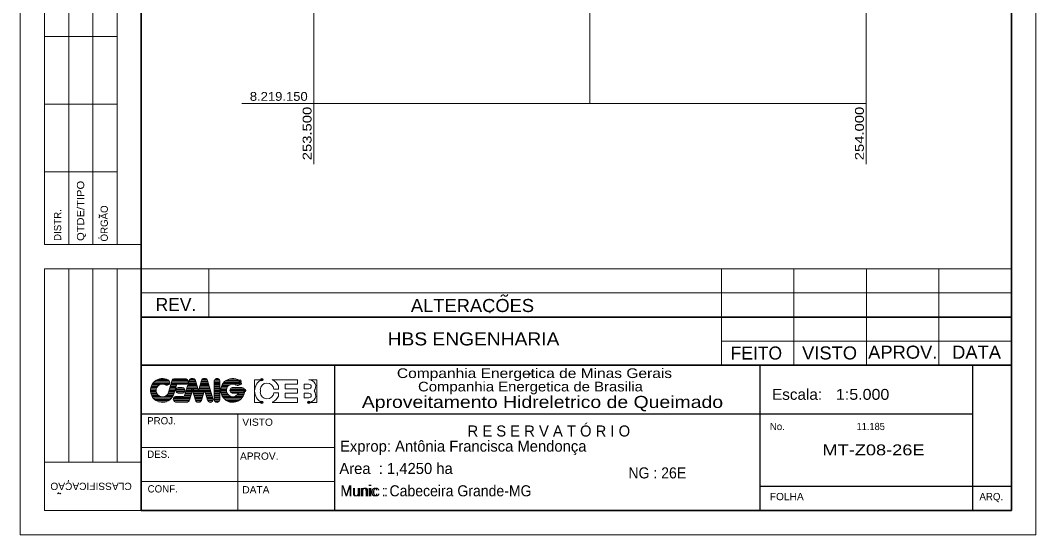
# Model space of a CAD drawing. Extents: x 253235 to 254153, y 8218760 to 8220059.
# Drawn here: x 253235 to 254153, y 8218760 to 8219225 of the extents above; entities that cross this region are included whole.
import ezdxf
from ezdxf.enums import TextEntityAlignment as Align

# ---------------------------------------------------------------- set-up
doc = ezdxf.new("R2010")
doc.units = 0
doc.header["$LTSCALE"] = 4.7
doc.header["$PDMODE"] = 32
doc.header["$PDSIZE"] = 2.35
doc.layers.add('6', color=7, linetype='Continuous', lineweight=13)

msp = doc.modelspace()

# ---------------------------------------------------------------- linework, layer by layer
at = {"layer": '6'}
for p, q in [((253500, 8219095), (253500, 8219900)), ((253750, 8219150), (253750, 8219900)), ((254000, 8219095), (254000, 8219900)), ((253256.41, 8219766.08), (253256.41, 8219022.38)), ((253278.31, 8219766.08), (253278.31, 8219022.38)), ((253300.11, 8219022.38), (253300.11, 8219766.08)), ((253322.01, 8219766.08), (253322.01, 8219022.38)), ((253256.41, 8219210.48), (253322.01, 8219210.48)), ((253256.41, 8219149.28), (253322.01, 8219149.28)), ((253435, 8219150), (254000, 8219150)), ((253256.41, 8219088.08), (253322.01, 8219088.08)), ((253306.31, 8219028.08), (253305.11, 8219028.48)), ((253343.91, 8219022.38), (253256.41, 8219022.38)), ((253278.31, 8218825.48), (253278.31, 8219000.48)), ((253300.11, 8218825.48), (253300.11, 8219000.48)), ((253322.01, 8218825.48), (253322.01, 8219000.48)), ((253343.91, 8219000.48), (254131.41, 8219000.48)), ((253405.11, 8218957.08), (253405.11, 8219000.48)), ((253868.91, 8218913.08), (253868.91, 8219000.48)), ((253934.51, 8219000.48), (253934.51, 8218913.08)), ((254000.11, 8218913.08), (254000.11, 8219000.48)), ((254065.71, 8219000.48), (254065.71, 8218913.08)), ((253343.91, 8218978.68), (254131.41, 8218978.68)), ((253659.91, 8218961.77), (253659.51, 8218960.37)), ((253868.91, 8218934.88), (254131.41, 8218934.88)), ((253353.91, 8218896.08), (253362.71, 8218896.08)), ((253354.71, 8218897.08), (253369.61, 8218897.08)), ((253355.71, 8218898.18), (253369.61, 8218898.18)), ((253356.91, 8218899.28), (253369.11, 8218899.28)), ((253358.91, 8218900.28), (253367.31, 8218900.28)), ((253363.51, 8218896.08), (253369.21, 8218896.08)), ((253371.71, 8218898.88), (253368.61, 8218888.68)), ((253370.91, 8218896.08), (253384.91, 8218896.08)), ((253371.11, 8218897.08), (253386.11, 8218897.08)), ((253371.51, 8218898.18), (253386.41, 8218898.18)), ((253371.71, 8218899.28), (253386.31, 8218899.28)), ((253372.51, 8218900.28), (253385.61, 8218900.28)), ((253383.91, 8218900.88), (253374.11, 8218900.88)), ((253376.91, 8218895.88), (253383.91, 8218895.88)), ((253383.21, 8218885.68), (253387.41, 8218899.28)), ((253386.71, 8218896.68), (253393.71, 8218896.68)), ((253386.91, 8218897.88), (253393.31, 8218897.88)), ((253387.31, 8218898.88), (253393.11, 8218898.88)), ((253387.71, 8218899.88), (253392.71, 8218899.88)), ((253388.91, 8218900.98), (253391.31, 8218900.98)), ((253397.71, 8218896.68), (253404.71, 8218896.68)), ((253398.01, 8218897.88), (253404.51, 8218897.88)), ((253398.31, 8218898.88), (253404.11, 8218898.88)), ((253398.71, 8218899.88), (253403.71, 8218899.88)), ((253400.01, 8218900.98), (253402.51, 8218900.98)), ((253403.91, 8218899.48), (253408.71, 8218883.08)), ((253409.91, 8218898.88), (253415.11, 8218898.88)), ((253409.91, 8218882.08), (253409.91, 8218898.48)), ((253409.91, 8218897.68), (253415.11, 8218897.68)), ((253409.91, 8218896.68), (253415.11, 8218896.68)), ((253410.31, 8218899.88), (253414.71, 8218899.88)), ((253411.51, 8218900.88), (253413.61, 8218900.88)), ((253415.11, 8218898.68), (253415.11, 8218882.08)), ((253417.91, 8218896.68), (253433.61, 8218896.68)), ((253418.71, 8218897.68), (253433.71, 8218897.68)), ((253419.91, 8218898.68), (253433.31, 8218898.68)), ((253421.31, 8218899.78), (253432.11, 8218899.78)), ((253424.11, 8218900.88), (253429.41, 8218900.88)), ((253495.71, 8218895.98), (253491.51, 8218895.98)), ((253352.31, 8218890.68), (253357.41, 8218890.68)), ((253352.31, 8218889.68), (253357.51, 8218889.68)), ((253352.41, 8218891.88), (253357.71, 8218891.88)), ((253352.41, 8218888.68), (253357.71, 8218888.68)), ((253352.71, 8218892.88), (253358.01, 8218892.88)), ((253352.71, 8218887.58), (253358.11, 8218887.58)), ((253352.91, 8218893.88), (253358.71, 8218893.88)), ((253353.41, 8218894.98), (253359.81, 8218894.98)), ((253368.11, 8218887.58), (253373.61, 8218887.58)), ((253368.51, 8218888.68), (253373.91, 8218888.68)), ((253368.91, 8218889.68), (253374.31, 8218889.68)), ((253369.21, 8218890.68), (253374.51, 8218890.68)), ((253369.51, 8218891.88), (253374.91, 8218891.88)), ((253369.91, 8218892.88), (253375.11, 8218892.88)), ((253370.21, 8218893.88), (253375.51, 8218893.88)), ((253370.51, 8218894.98), (253375.81, 8218894.98)), ((253373.51, 8218887.28), (253375.91, 8218895.08)), ((253375.31, 8218891.18), (253383.31, 8218891.18)), ((253375.31, 8218890.08), (253383.51, 8218890.08)), ((253375.51, 8218889.08), (253383.11, 8218889.08)), ((253376.11, 8218892.28), (253382.71, 8218892.28)), ((253376.91, 8218887.98), (253381.91, 8218887.98)), ((253377.71, 8218892.88), (253380.91, 8218892.88)), ((253380.91, 8218887.88), (253377.71, 8218887.88)), ((253383.71, 8218887.28), (253389.31, 8218887.28)), ((253384.11, 8218888.28), (253389.61, 8218888.28)), ((253384.31, 8218889.28), (253389.91, 8218889.28)), ((253384.71, 8218890.38), (253390.31, 8218890.38)), ((253385.01, 8218891.48), (253395.31, 8218891.48)), ((253385.31, 8218892.48), (253394.91, 8218892.48)), ((253385.71, 8218893.58), (253394.61, 8218893.58)), ((253386.01, 8218894.68), (253394.31, 8218894.68)), ((253386.31, 8218895.68), (253394.01, 8218895.68)), ((253390.31, 8218890.38), (253395.51, 8218890.38)), ((253390.61, 8218889.28), (253400.81, 8218889.28)), ((253390.91, 8218888.28), (253400.51, 8218888.28)), ((253391.21, 8218887.28), (253400.21, 8218887.28)), ((253395.81, 8218890.38), (253401.11, 8218890.38)), ((253396.11, 8218891.48), (253406.31, 8218891.48)), ((253396.41, 8218892.48), (253405.91, 8218892.48)), ((253396.71, 8218893.58), (253405.71, 8218893.58)), ((253397.11, 8218894.68), (253405.31, 8218894.68)), ((253397.31, 8218895.68), (253405.01, 8218895.68)), ((253401.21, 8218890.68), (253398.41, 8218881.28)), ((253403.91, 8218881.68), (253401.31, 8218890.68)), ((253401.31, 8218890.38), (253406.61, 8218890.38)), ((253401.71, 8218889.28), (253406.91, 8218889.28)), ((253401.91, 8218888.28), (253407.31, 8218888.28)), ((253402.31, 8218887.28), (253407.51, 8218887.28)), ((253409.91, 8218895.68), (253415.11, 8218895.68)), ((253409.91, 8218894.58), (253415.11, 8218894.58)), ((253409.91, 8218893.48), (253415.11, 8218893.48)), ((253409.91, 8218892.48), (253415.11, 8218892.48)), ((253409.91, 8218891.48), (253415.11, 8218891.48)), ((253409.91, 8218890.38), (253415.11, 8218890.38)), ((253409.91, 8218889.28), (253415.11, 8218889.28)), ((253409.91, 8218888.28), (253415.11, 8218888.28)), ((253409.91, 8218887.18), (253415.11, 8218887.18)), ((253415.91, 8218891.28), (253421.11, 8218891.28)), ((253415.91, 8218890.28), (253421.01, 8218890.28)), ((253416.01, 8218889.18), (253421.11, 8218889.18)), ((253416.11, 8218892.38), (253421.31, 8218892.38)), ((253416.11, 8218888.08), (253421.51, 8218888.08)), ((253416.41, 8218893.48), (253421.91, 8218893.48)), ((253416.51, 8218887.08), (253422.11, 8218887.08)), ((253416.71, 8218894.48), (253422.71, 8218894.48)), ((253417.21, 8218895.48), (253424.31, 8218895.48)), ((253424.11, 8218890.28), (253437.51, 8218890.28)), ((253424.31, 8218891.28), (253437.31, 8218891.28)), ((253424.51, 8218889.18), (253437.51, 8218889.18)), ((253425.11, 8218892.38), (253436.51, 8218892.38)), ((253425.51, 8218888.08), (253437.31, 8218888.08)), ((253435.11, 8218892.88), (253426.71, 8218892.88)), ((253426.71, 8218887.88), (253431.91, 8218887.88)), ((253429.11, 8218895.48), (253433.01, 8218895.48)), ((253431.41, 8218887.08), (253437.01, 8218887.08)), ((253451.71, 8218890.88), (253451.71, 8218888.88)), ((253463.91, 8218888.28), (253468.01, 8218888.28)), ((253468.01, 8218885.08), (253468.01, 8218888.28)), ((253495.71, 8218887.78), (253491.51, 8218887.78)), ((253353.11, 8218886.48), (253358.91, 8218886.48)), ((253353.51, 8218885.48), (253360.11, 8218885.48)), ((253354.11, 8218884.48), (253372.11, 8218884.48)), ((253354.91, 8218883.38), (253371.31, 8218883.38)), ((253355.91, 8218882.28), (253370.31, 8218882.28)), ((253357.31, 8218881.28), (253368.91, 8218881.28)), ((253359.51, 8218880.18), (253366.71, 8218880.18)), ((253366.11, 8218885.48), (253372.71, 8218885.48)), ((253367.41, 8218886.48), (253373.31, 8218886.48)), ((253372.91, 8218881.88), (253387.71, 8218881.88)), ((253373.01, 8218883.08), (253388.11, 8218883.08)), ((253373.31, 8218880.88), (253387.31, 8218880.88)), ((253373.51, 8218884.08), (253388.41, 8218884.08)), ((253375.01, 8218879.78), (253385.71, 8218879.78)), ((253375.51, 8218884.88), (253382.11, 8218884.88)), ((253385.11, 8218879.78), (253375.51, 8218879.78)), ((253382.91, 8218885.08), (253388.71, 8218885.08)), ((253383.41, 8218886.18), (253389.01, 8218886.18)), ((253391.51, 8218886.18), (253399.91, 8218886.18)), ((253391.91, 8218885.08), (253399.51, 8218885.08)), ((253392.11, 8218884.08), (253399.31, 8218884.08)), ((253392.51, 8218883.08), (253398.91, 8218883.08)), ((253392.81, 8218881.88), (253398.61, 8218881.88)), ((253393.11, 8218880.88), (253398.31, 8218880.88)), ((253394.31, 8218879.78), (253397.11, 8218879.78)), ((253402.51, 8218886.18), (253407.91, 8218886.18)), ((253402.91, 8218885.08), (253408.11, 8218885.08)), ((253403.11, 8218884.08), (253408.51, 8218884.08)), ((253403.51, 8218883.08), (253408.71, 8218883.08)), ((253403.81, 8218881.88), (253408.91, 8218881.88)), ((253404.11, 8218880.88), (253408.61, 8218880.88)), ((253405.31, 8218879.78), (253407.51, 8218879.78)), ((253409.91, 8218886.08), (253415.11, 8218886.08)), ((253409.91, 8218885.08), (253415.11, 8218885.08)), ((253409.91, 8218883.98), (253415.11, 8218883.98)), ((253409.91, 8218882.88), (253415.11, 8218882.88)), ((253409.91, 8218881.88), (253415.11, 8218881.88)), ((253410.31, 8218880.78), (253414.71, 8218880.78)), ((253411.51, 8218879.78), (253413.51, 8218879.78)), ((253416.91, 8218885.98), (253423.11, 8218885.98)), ((253417.41, 8218884.88), (253424.91, 8218884.88)), ((253418.11, 8218883.88), (253435.31, 8218883.88)), ((253418.91, 8218882.78), (253434.51, 8218882.78)), ((253420.21, 8218881.68), (253433.31, 8218881.68)), ((253421.91, 8218880.68), (253431.51, 8218880.68)), ((253425.31, 8218879.68), (253428.11, 8218879.68)), ((253428.51, 8218884.88), (253436.11, 8218884.88)), ((253430.51, 8218885.98), (253436.61, 8218885.98)), ((253431.41, 8218869.28), (253431.41, 8218781.78)), ((253343.91, 8218838.68), (253518.91, 8218838.68)), ((253256.41, 8218825.48), (253343.91, 8218825.48)), ((253277.71, 8218807.38), (253278.21, 8218809.08)), ((253343.91, 8218808.08), (253518.91, 8218808.08))]:
    msp.add_line(p, q, dxfattribs=at)
at = {"layer": '6', "lineweight": 35}
for p, q in [((253343.91, 8218956.78), (254131.41, 8218956.78)), ((253343.91, 8218913.08), (254131.41, 8218913.08))]:
    msp.add_line(p, q, dxfattribs=at)
at = {"layer": '6', "lineweight": 25}
for p, q in [((253518.91, 8218913.08), (253518.91, 8218781.78)), ((253694.71, 8218903.88), (253696.51, 8218906.08)), ((253903.91, 8218781.78), (253903.91, 8218913.08)), ((254096.41, 8218781.78), (254096.41, 8218913.08)), ((253343.91, 8218869.28), (254096.41, 8218869.28)), ((253903.91, 8218803.68), (254131.41, 8218803.68))]:
    msp.add_line(p, q, dxfattribs=at)
at = {"layer": '6'}
msp.add_lwpolyline([(253234.51, 8218759.88), (254153.31, 8218759.88), (254153.31, 8220059.28), (253234.51, 8220059.28)], close=True, dxfattribs=at)
at = {"layer": '6', "lineweight": 35}
msp.add_lwpolyline([(253343.91, 8218781.78), (254131.41, 8218781.78), (254131.41, 8220037.38), (253343.91, 8220037.38)], close=True, dxfattribs=at)
at = {"layer": '6'}
for points in [[(253343.91, 8218781.78), (253256.41, 8218781.78), (253256.41, 8219000.48), (253343.91, 8219000.48)], [(253383.91, 8218900.88), (253374.11, 8218900.88), (253383.91, 8218900.88)], [(253392.91, 8218899.28), (253395.71, 8218890.08), (253398.51, 8218899.38)], [(253453.11, 8218900.08), (253446.51, 8218900.08), (253446.51, 8218889.88)], [(253462.51, 8218900.08), (253485.41, 8218900.08), (253485.41, 8218895.98), (253474.21, 8218895.98), (253474.21, 8218891.88), (253485.41, 8218891.88), (253485.41, 8218887.78), (253474.21, 8218887.78), (253474.21, 8218883.68), (253485.41, 8218883.68), (253485.41, 8218879.58), (253462.51, 8218879.58)], [(253491.51, 8218895.98), (253491.51, 8218891.88), (253495.71, 8218891.88)], [(253495.71, 8218879.58), (253502.91, 8218879.58), (253502.91, 8218900.08), (253495.71, 8218900.08)], [(253377.71, 8218892.88), (253380.91, 8218892.88), (253377.71, 8218892.88)], [(253392.91, 8218881.48), (253390.31, 8218890.38), (253387.71, 8218881.68)], [(253446.51, 8218889.88), (253446.51, 8218879.58), (253453.11, 8218879.58)], [(253463.91, 8218891.38), (253468.01, 8218891.38), (253468.01, 8218894.48)], [(253491.51, 8218887.78), (253491.51, 8218883.68), (253495.71, 8218883.68)]]:
    msp.add_lwpolyline(points, dxfattribs=at)
for centre, radius, start, end in [((253363.159, 8218890.385), 10.81, 60.51986, 343.11893), ((253363.159, 8218890.385), 5.723, 61.72795, 343.03727), ((253367.165, 8218897.613), 2.544, 235.21396, 65.35832), ((253374.223, 8218898.44), 2.544, 87.13759, 170.18874), ((253376.891, 8218894.836), 1.06, 89.99996, 162.02084), ((253383.889, 8218898.44), 2.544, 265.44623, 91.43209), ((253389.867, 8218898.652), 2.544, 82.81573, 166.414), ((253390.503, 8218898.652), 2.544, 14.03624, 98.40891), ((253400.889, 8218898.652), 2.544, 81.3986, 168.03793), ((253401.525, 8218898.652), 2.544, 10.56101, 98.60138), ((253412.547, 8218898.652), 2.544, 355.4978, 183.81406), ((253412.547, 8218898.652), 2.544, 355.4978, 183.81406), ((253412.547, 8218898.652), 2.544, 355.49781, 183.81406), ((253426.749, 8218890.385), 10.81, 56.684, 0.67404), ((253426.749, 8218890.385), 5.723, 57.02091, 333.72578), ((253431.201, 8218897.338), 2.544, 231.58194, 58.45584), ((253431.201, 8218897.338), 2.544, 231.58194, 58.45584), ((253431.201, 8218897.338), 2.544, 231.58194, 58.45584), ((253457.816, 8218889.874), 11.261, 114.61998, 180), ((253457.816, 8218890.898), 6.143, 4.78019, 180), ((253457.816, 8218889.874), 11.261, 24.61998, 65.38002), ((253495.695, 8218893.969), 6.143, 318.18969, 90), ((253495.695, 8218893.969), 2.047, 270, 90), ((253377.784, 8218890.385), 2.544, 84.2894, 274.28914), ((253380.964, 8218890.385), 2.544, 265.04973, 90.95483), ((253426.749, 8218890.385), 2.544, 85.19651, 273.81407), ((253435.016, 8218890.385), 2.544, 354.20078, 95.23747), ((253457.816, 8218889.874), 11.261, 180, 245.38002), ((253457.816, 8218888.85), 6.143, 180, 355.21981), ((253495.695, 8218885.779), 6.143, 270, 41.81031), ((253495.695, 8218885.779), 2.047, 270, 90), ((253375.453, 8218882.33), 2.544, 89.52254, 273.57633), ((253375.453, 8218882.33), 2.544, 89.52254, 273.57633), ((253375.453, 8218882.33), 2.544, 89.52254, 273.57633), ((253382.229, 8218885.934), 1.06, 269.99998, 343.09819), ((253385.203, 8218882.33), 2.544, 264.94274, 348.40781), ((253395.378, 8218882.118), 2.544, 192.99461, 278.60138), ((253396.014, 8218882.118), 2.544, 261.07601, 342.47442), ((253406.4, 8218882.118), 2.544, 190.56101, 24.36245), ((253412.547, 8218882.118), 2.544, 179.05304, 4.18491), ((253457.816, 8218889.874), 11.261, 294.61998, 335.38002)]:
    msp.add_arc(centre, radius, start, end, dxfattribs=at)
for points in [[(253306.31, 8219046.48), (253305.71, 8219046.88), (253306.11, 8219047.88), (253306.51, 8219048.48), (253305.61, 8219049.28)], [(253669.4, 8218975.38), (253670.5, 8218976.48), (253671.9, 8218976.88), (253673, 8218975.68), (253673.5, 8218975.48), (253674.5, 8218975.68), (253675.6, 8218977.08)], [(253271.11, 8218797.48), (253270.71, 8218796.88), (253269.51, 8218797.28), (253269.01, 8218797.78), (253268.31, 8218796.88)]]:
    msp.add_spline(points, degree=3, dxfattribs=at)
for p in [(253433.31, 8218898.68), (253433.61, 8218896.68), (253453.11, 8218900.08), (253390.31, 8218890.38), (253437.51, 8218890.28), (253453.11, 8218879.58), (253495.71, 8218879.58)]:
    msp.add_point(p, dxfattribs=at)

# ---------------------------------------------------------------- texts
for s, height, width, p in [('8.219.150', 8, 1.1, (253468.38, 8219152.32)), ('Escala: ', 9.844, 1.05, (253939.3, 8218881.87)), ('1:5.000', 9.84, 1.1, (253996.71, 8218881.87)), ('Aproveitamento Hidreletrico de Queimado', 10.94, 1.2, (253706.975, 8218874.47)), ('MT-Z08-26E', 9.844, 1.25, (254006.545, 8218831.67)), ('NG : 26E', 10, 0.95, (253810.91, 8218810.77))]:
    msp.add_text(s, height=height, dxfattribs=dict(at, width=width)).set_placement(p, align=Align.CENTER)
at = {"layer": '6', "width": 1.25}
for s, p in [('253.500', (253498.01, 8219122.755)), ('254.000', (253997.79, 8219122.755))]:
    msp.add_text(s, height=8, rotation=90, dxfattribs=at).set_placement(p, align=Align.CENTER)
at = {"layer": '6'}
for s, rotation, width, p in [('QTDE/TIPO', 90, 1.15, (253292.31, 8219025.57)), ('CLASSIFICACAO', 180, 1.05, (253335.41, 8218806.87))]:
    msp.add_text(s, height=6.562, rotation=rotation, dxfattribs=dict(at, width=width)).set_placement(p)
for s, p in [('DISTR.', (253271.51, 8219025.57)), ('ORGAO', (253313.71, 8219025.07))]:
    msp.add_text(s, height=6.562, rotation=90, dxfattribs=at).set_placement(p)
for s, height, p in [('REV.', 11.81, (253356.91, 8218962.17)), ('FEITO', 11.81, (253877.31, 8218918.27)), ('PROJ.', 6.562, (253349.31, 8218859.67)), ('No.', 6.562, (253912.71, 8218854.47)), ('Exprop: Antônia Francisca Mendonça', 10, (253523.81, 8218834.97)), ('Exprop: ', 10, (253523.81, 8218834.97)), ('DES.', 6.562, (253349.31, 8218829.37)), ('Area  : 1,4250 ha', 10, (253523.21, 8218814.77)), ('CONF.', 6.562, (253349.71, 8218798.07)), ('Munic : ', 10, (253524.11, 8218794.57)), ('ARQ.', 6.562, (254102.41, 8218791.07))]:
    msp.add_text(s, height=height, dxfattribs=at).set_placement(p)
for s, height, width, p in [('ALTERACOES', 11.81, 1.05, (253587.91, 8218961.27)), ('HBS ENGENHARIA', 11.81, 1.1, (253566.91, 8218931.07)), ('VISTO', 11.81, 1.05, (253941.91, 8218918.37)), ('APROV.', 11.81, 1.05, (254001.71, 8218919.07)), ('DATA', 11.81, 1.05, (254077.71, 8218919.07)), ('Companhia Energetica de Minas Gerais', 8.75, 1.2, (253575.31, 8218901.57)), ('Companhia Energetica de Brasilia', 8.75, 1.15, (253594.41, 8218889.47)), ('VISTO', 6.562, 1.05, (253435.41, 8218858.37)), ('11.185', 6.562, 0.95, (253991.31, 8218854.47)), ('APROV.', 6.562, 1.05, (253433.31, 8218827.67)), ('DATA', 6.562, 1.05, (253435.41, 8218797.27)), ('Munic : Cabeceira Grande-MG', 10, 0.95, (253524.11, 8218794.57)), ('FOLHA', 6.562, 1.05, (253912.71, 8218791.07))]:
    msp.add_text(s, height=height, dxfattribs=dict(at, width=width)).set_placement(p)
msp.add_text('R E S E R V A T Ó R I O', height=10, dxfattribs=at).set_placement((253712.755, 8218848.67), align=Align.CENTER)

doc.saveas('drawing.dxf')
